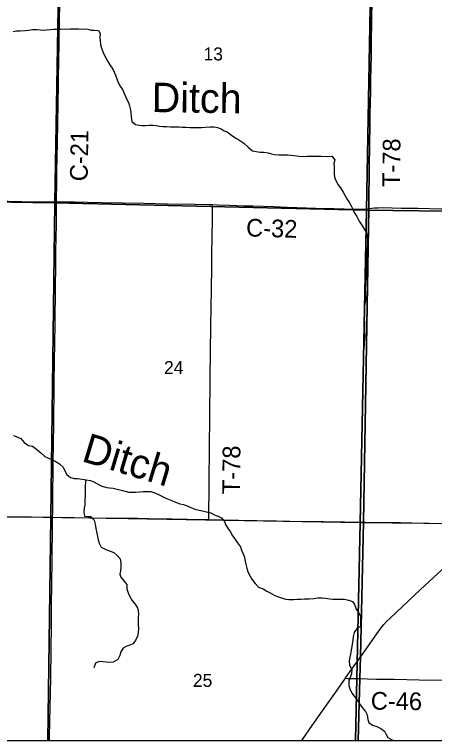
# Model space of a CAD drawing. Extents: x -8.5 to 18.7, y -20.3 to 7.
# Drawn here: x 9.055 to 11.753, y -20.262 to -15.596 of the extents above; entities that cross this region are included whole.
import ezdxf

# ---------------------------------------------------------------- set-up
doc = ezdxf.new("R2010")
doc.units = 0
for name, color, linetype in [('GM_X_Corporation', 7, 'Continuous'), ('GM_X_County_Road', 7, 'Continuous'), ('GM_X_County_Road_Text', 7, 'Continuous'), ('GM_X_Minor_River', 7, 'Continuous'), ('GM_X_Minor_River_Text', 7, 'Continuous'), ('GM_X_Section', 7, 'Continuous'), ('GM_X_Section_Text', 7, 'Continuous'), ('GM_X_State_Route', 7, 'Continuous'), ('GM_X_Township_Road', 7, 'Continuous'), ('GM_X_Township_Road_Text', 7, 'Continuous'), ('GM_X_Unincorporated_Text', 7, 'Continuous'), ('SH_Cut_Line', 7, 'Continuous')]:
    doc.layers.add(name, color=color, linetype=linetype)

msp = doc.modelspace()

# ---------------------------------------------------------------- linework, layer by layer
at = {"layer": 'GM_X_Corporation'}
for points in [[(-0.9232, -20.262), (11.2623, -20.262), (11.2736, -19.8636), (11.277, -19.7245), (11.2969, -18.8581), (11.3321, -16.8414), (11.3313, -16.8312), (11.331, -16.8266), (11.3309, -16.7927), (11.3361, -16.4073), (11.3374, -16.324), (11.339, -16.2358), (11.3417, -16.0903), (11.343, -16.0108), (11.3457, -15.8603), (11.3472, -15.7708), (11.351, -15.4961)], [(11.351, -15.4961), (11.3472, -15.7708), (11.3457, -15.8603), (11.343, -16.0108), (11.3417, -16.0903), (11.339, -16.2358), (11.3374, -16.324), (11.3361, -16.4073), (11.3309, -16.7927), (11.331, -16.8266), (11.3313, -16.8312), (11.3321, -16.8414), (11.2969, -18.8581), (11.277, -19.7245), (11.2736, -19.8636), (11.2623, -20.262), (18.7413, -20.262)]]:
    msp.add_lwpolyline(points, dxfattribs=at)
at = {"layer": 'GM_X_County_Road'}
for points in [[(9.3259, -16.7991), (9.326, -16.7709), (9.3266, -16.6901), (9.3279, -16.6018), (9.3308, -16.4216), (9.335, -16.1655), (9.3375, -16.0536), (9.3386, -15.9952), (9.3398, -15.9069), (9.3425, -15.7689), (9.3454, -15.6123), (9.3458, -15.5439), (9.3465, -15.5029), (9.3479, -15.4171), (9.3498, -15.3413), (9.3554, -15.0343), (9.3572, -14.9385), (9.3599, -14.7935)], [(7.3471, -16.771), (7.5621, -16.7748), (7.6354, -16.7759), (7.7299, -16.7774), (7.7908, -16.7785), (7.8902, -16.7802), (7.9735, -16.7818), (8.1998, -16.7851), (8.3067, -16.7862), (8.5131, -16.7898), (8.5566, -16.7903), (8.615, -16.7911), (8.7393, -16.7925), (8.8102, -16.7933), (8.9072, -16.7947), (9.0154, -16.7963), (9.1024, -16.7972), (9.264, -16.7988), (9.3137, -16.7991), (9.3259, -16.7991)], [(9.3003, -18.8271), (9.3007, -18.8058), (9.3006, -18.7374), (9.3021, -18.6504), (9.3042, -18.551), (9.3043, -18.4839), (9.306, -18.3496), (9.3078, -18.234), (9.3086, -18.1395), (9.3093, -18.0613), (9.3104, -17.9755), (9.3131, -17.8089), (9.3139, -17.7206), (9.3158, -17.574), (9.3187, -17.3564), (9.3206, -17.2047), (9.3216, -17.1289), (9.3233, -17.0182), (9.3245, -16.9574), (9.3246, -16.9101), (9.3258, -16.8305), (9.3259, -16.7991)], [(9.3259, -16.7991), (9.3966, -16.8), (9.4414, -16.8008), (9.5234, -16.8026), (9.6166, -16.804), (9.8864, -16.8089), (10.038, -16.812), (10.2133, -16.815), (10.3053, -16.8169), (10.3269, -16.8173)], [(10.3269, -16.8173), (10.3562, -16.818), (10.4358, -16.821), (10.5264, -16.8244), (10.5873, -16.8261), (10.7215, -16.8305), (10.8072, -16.8337), (10.9302, -16.8375), (11.0495, -16.8416), (11.1079, -16.8433), (11.2372, -16.8472), (11.2657, -16.8474), (11.2842, -16.8466), (11.3139, -16.8443), (11.3326, -16.8425)], [(11.3326, -16.8425), (11.3671, -16.8392), (11.392, -16.8377), (11.4257, -16.8371), (11.4804, -16.8379), (11.5413, -16.8394), (11.6494, -16.841), (11.7961, -16.8438), (11.8446, -16.8445), (12.0534, -16.8489), (12.1603, -16.8513), (12.2958, -16.8534), (12.4375, -16.8563), (12.4873, -16.8575), (12.532, -16.8584), (12.6066, -16.8592), (12.6538, -16.8603), (12.7657, -16.8621), (12.9099, -16.8649), (13.0167, -16.8667), (13.1821, -16.8697), (13.2828, -16.8711), (13.3593, -16.8726)], [(9.2795, -20.262), (9.2801, -20.2354), (9.2869, -19.9508), (9.289, -19.8662), (9.2893, -19.8078), (9.2903, -19.732), (9.2908, -19.635), (9.292, -19.5642), (9.2938, -19.3913), (9.2957, -19.2571), (9.2974, -19.0992), (9.2988, -18.8891), (9.3003, -18.8271)], [(11.1806, -19.862), (11.1973, -19.8626), (11.2363, -19.8639), (11.2741, -19.8647)], [(11.2741, -19.8647), (11.3221, -19.8657), (11.3817, -19.8672), (11.4936, -19.8684), (11.6552, -19.8712), (11.9747, -19.8761), (12.0692, -19.8767), (12.1997, -19.8796), (12.2954, -19.8809), (12.3998, -19.8829), (12.646, -19.8869), (12.7603, -19.8886), (12.8871, -19.8909), (13.0139, -19.8932), (13.0972, -19.8946), (13.1854, -19.8963), (13.3025, -19.8984)]]:
    msp.add_lwpolyline(points, dxfattribs=at)
at = {"layer": 'GM_X_Minor_River'}
for points in [[(9.0478, -15.7058), (9.0683, -15.7014), (9.0918, -15.7), (9.1236, -15.6994), (9.1456, -15.6957), (9.1699, -15.692), (9.1986, -15.6914), (9.2198, -15.6937)], [(9.2198, -15.6937), (9.2403, -15.6953), (9.26, -15.6947), (9.2858, -15.6925), (9.3062, -15.6903), (9.3274, -15.6897), (9.3509, -15.689), (9.3752, -15.6884), (9.3956, -15.6892), (9.4153, -15.6886), (9.4426, -15.6879), (9.4676, -15.6881), (9.4873, -15.6897), (9.507, -15.6882), (9.5274, -15.6906), (9.5471, -15.6953), (9.5675, -15.6969), (9.594, -15.6985), (9.6053, -15.7183), (9.603, -15.7433), (9.6052, -15.7631), (9.6081, -15.7889), (9.6148, -15.8117), (9.6283, -15.8497), (9.6426, -15.8748), (9.6546, -15.8968), (9.6674, -15.9189), (9.6862, -15.9463), (9.6945, -15.9668), (9.7043, -15.9866), (9.714, -16.0162), (9.7238, -16.036), (9.7335, -16.0557), (9.7486, -16.0778), (9.7584, -16.0968), (9.7689, -16.1219), (9.7779, -16.1417), (9.7884, -16.1622), (9.7944, -16.182), (9.8011, -16.2078), (9.8018, -16.2268), (9.804, -16.2533), (9.8092, -16.2837), (9.8326, -16.302), (9.856, -16.3074), (9.8757, -16.3091), (9.8969, -16.3084), (9.9212, -16.3062), (9.9439, -16.3063), (9.9659, -16.3095), (9.9871, -16.3126), (10.0083, -16.315), (10.031, -16.3159), (10.0567, -16.3175), (10.081, -16.3184), (10.1135, -16.3185), (10.1332, -16.3194), (10.1552, -16.3195), (10.1817, -16.3211), (10.2029, -16.3212), (10.2309, -16.3221), (10.2559, -16.3214), (10.2832, -16.3208), (10.312, -16.3187), (10.3363, -16.3173), (10.3597, -16.3212), (10.3824, -16.3311), (10.4021, -16.3426), (10.4225, -16.3495), (10.4497, -16.3709), (10.4776, -16.3908), (10.4973, -16.4007), (10.5275, -16.4221), (10.5554, -16.4473), (10.5841, -16.4709), (10.6068, -16.4771), (10.6326, -16.4802), (10.6568, -16.4804), (10.6841, -16.4843), (10.7052, -16.4912), (10.7257, -16.4951), (10.7537, -16.4967), (10.8098, -16.497), (10.8294, -16.5001), (10.8537, -16.5018), (10.8824, -16.5057), (10.9067, -16.5073), (10.9324, -16.5067), (10.9536, -16.506), (10.9847, -16.5069), (11.0044, -16.5062), (11.0256, -16.5071), (11.0688, -16.5073), (11.0945, -16.5067), (11.1134, -16.5303), (11.1072, -16.5538), (11.1079, -16.5727), (11.1093, -16.5978), (11.1085, -16.6167), (11.1099, -16.641), (11.1204, -16.6623)], [(11.1204, -16.6623), (11.1347, -16.6897), (11.149, -16.7087), (11.1656, -16.7369), (11.1799, -16.7605), (11.1904, -16.7802), (11.2078, -16.8054), (11.2183, -16.8244), (11.2296, -16.8479), (11.237, -16.8692), (11.2551, -16.8943), (11.2694, -16.9232), (11.2822, -16.943), (11.2988, -16.9704), (11.3146, -16.9948), (11.3213, -17.0175), (11.3235, -17.0464), (11.3234, -17.0729), (11.3202, -17.1018), (11.3186, -17.1215), (11.317, -17.1427), (11.3185, -17.1617), (11.3176, -17.1814), (11.3168, -17.2026), (11.3159, -17.2284), (11.3136, -17.2534), (11.3135, -17.2724), (11.3126, -17.2944), (11.3103, -17.3141), (11.3095, -17.3331), (11.3086, -17.3581), (11.31, -17.3854), (11.3107, -17.4105), (11.3091, -17.4347), (11.3067, -17.4545), (11.3036, -17.4734), (11.3012, -17.4992), (11.3026, -17.525), (11.3025, -17.5508), (11.3047, -17.5766), (11.3045, -17.6312), (11.3059, -17.6525), (11.3035, -17.6813), (11.3019, -17.7071), (11.3011, -17.7268)], [(9.0483, -18.302), (9.0763, -18.312)], [(9.0763, -18.312), (9.0959, -18.3204), (9.117, -18.347), (9.1457, -18.3654), (9.1707, -18.3708), (9.1956, -18.3899), (9.2236, -18.4135), (9.2492, -18.4372), (9.2689, -18.4456), (9.2901, -18.4533), (9.3165, -18.4671), (9.3445, -18.4846), (9.3686, -18.506), (9.3807, -18.5326), (9.392, -18.5516), (9.4146, -18.5707), (9.4396, -18.5784), (9.4593, -18.5785), (9.4895, -18.5824), (9.5153, -18.5863), (9.544, -18.5918), (9.5645, -18.6002), (9.5849, -18.6102), (9.6121, -18.6254), (9.6454, -18.6362), (9.6658, -18.6371), (9.6901, -18.6402), (9.7415, -18.6541), (9.7657, -18.6603), (9.7907, -18.6665), (9.8134, -18.6666), (9.8339, -18.6652), (9.8604, -18.6645), (9.8816, -18.6624), (9.9081, -18.661), (9.9301, -18.6618), (9.9505, -18.6672), (9.9755, -18.678), (10.0019, -18.6925), (10.0284, -18.704), (10.0488, -18.7124), (10.07, -18.7209), (10.0896, -18.7301), (10.1176, -18.7401), (10.1419, -18.7447), (10.1638, -18.7532), (10.188, -18.7654), (10.2137, -18.7754), (10.2409, -18.7816), (10.2621, -18.7862), (10.2894, -18.7924), (10.3159, -18.7994), (10.3446, -18.8139), (10.3643, -18.8201), (10.3854, -18.8308), (10.4035, -18.8536), (10.411, -18.8742), (10.4276, -18.9008), (10.4419, -18.9213), (10.4524, -18.9411), (10.4675, -18.9647), (10.4886, -18.9921), (10.5074, -19.018), (10.5141, -19.0385), (10.5231, -19.0575), (10.5299, -19.0772), (10.5373, -19.1084), (10.5418, -19.1281), (10.547, -19.1554), (10.5545, -19.179), (10.5688, -19.2056), (10.5808, -19.2254), (10.6004, -19.2535), (10.6238, -19.2756), (10.6525, -19.2879), (10.6759, -19.3032), (10.6971, -19.3139), (10.7281, -19.33), (10.7508, -19.3392), (10.7765, -19.3476), (10.7984, -19.353), (10.8181, -19.3562), (10.8484, -19.3548), (10.8704, -19.3534), (10.8939, -19.3535), (10.9181, -19.3513), (10.9492, -19.3515), (10.9787, -19.3501), (11.0037, -19.3457), (11.031, -19.3458), (11.0545, -19.3482), (11.081, -19.3521), (11.1007, -19.3537), (11.1211, -19.3546), (11.1431, -19.3547), (11.1726, -19.354), (11.2037, -19.3595), (11.2271, -19.3687), (11.2392, -19.3885), (11.2512, -19.4174), (11.267, -19.444)], [(9.5145, -18.5862), (9.5122, -18.6007), (9.5098, -18.6265), (9.5096, -18.6743), (9.5079, -18.7289), (9.5063, -18.7478), (9.5032, -18.7668), (9.5008, -18.7941), (9.506, -18.8199), (9.5265, -18.8223), (9.5462, -18.8216), (9.568, -18.846), (9.5732, -18.8725), (9.5784, -18.8999), (9.5851, -18.9287), (9.5881, -18.95), (9.5925, -18.9728), (9.5993, -18.9933), (9.6128, -19.0191), (9.6423, -19.0344), (9.6665, -19.0429), (9.6929, -19.0544), (9.7179, -19.0742), (9.7344, -19.0955), (9.7389, -19.1229), (9.738, -19.1524), (9.7364, -19.1714), (9.7325, -19.1926), (9.7378, -19.2124), (9.7581, -19.2352), (9.7777, -19.2588), (9.7776, -19.2869), (9.7851, -19.3134), (9.7994, -19.3401), (9.8099, -19.3591), (9.828, -19.3834), (9.8453, -19.4101), (9.8505, -19.429), (9.8512, -19.448), (9.8503, -19.4738), (9.8487, -19.4935), (9.8501, -19.5193), (9.8516, -19.5428), (9.8499, -19.5686), (9.8453, -19.5913), (9.8331, -19.6201), (9.8163, -19.6405), (9.7966, -19.6495), (9.7769, -19.6555), (9.7526, -19.6683), (9.7388, -19.6932), (9.7312, -19.7152), (9.7197, -19.7417), (9.6893, -19.759), (9.6666, -19.7611), (9.6462, -19.758), (9.6242, -19.7556), (9.6, -19.7548), (9.5757, -19.7645), (9.5657, -19.7948)], [(11.267, -19.444), (11.2775, -19.4637), (11.2774, -19.4865), (11.2781, -19.5062), (11.278, -19.529), (11.2575, -19.541), (11.2369, -19.5682), (11.2315, -19.5947), (11.2284, -19.6175), (11.2222, -19.6577), (11.2175, -19.6804), (11.2129, -19.7062), (11.2098, -19.7259), (11.2051, -19.7509), (11.2073, -19.7789), (11.2216, -19.8063), (11.2192, -19.8306), (11.2115, -19.8563), (11.2038, -19.8806), (11.2037, -19.9079), (11.2105, -19.9291), (11.2225, -19.9572), (11.2443, -19.9854), (11.2586, -20.0052), (11.2707, -20.0265), (11.2888, -20.0509), (11.3106, -20.0767), (11.3211, -20.098), (11.3248, -20.1269), (11.3323, -20.1459), (11.3542, -20.1634), (11.3837, -20.1711), (11.4087, -20.1841), (11.4328, -20.2025), (11.4418, -20.223), (11.4539, -20.242), (11.4818, -20.2588), (11.4903, -20.262)]]:
    msp.add_lwpolyline(points, dxfattribs=at)
at = {"layer": 'GM_X_Section'}
for points in [[(7.3681, -14.7705), (9.3493, -14.7982), (9.3147, -16.8052), (7.3365, -16.776)], [(9.3493, -14.7982), (11.3525, -14.8396), (11.3171, -16.8542), (9.3147, -16.8052)], [(11.3525, -14.8396), (11.3525, -14.8313), (13.3845, -14.866), (13.3536, -16.8784), (11.3171, -16.8542)], [(7.3365, -16.776), (9.3147, -16.8052), (9.2884, -18.8288), (7.2987, -18.8185)], [(9.3147, -16.8052), (11.3171, -16.8542), (11.2748, -18.8626), (9.2884, -18.8288)], [(11.3171, -16.8542), (13.3536, -16.8784), (13.322, -18.8853), (11.2748, -18.8626)]]:
    msp.add_lwpolyline(points, close=True, dxfattribs=at)
at = {"layer": 'GM_X_State_Route'}
for points in [[(11.2763, -19.7271), (11.2774, -19.7256), (11.3834, -19.5764), (11.4112, -19.537), (11.4283, -19.516), (11.4453, -19.498), (11.4687, -19.4748), (11.6608, -19.2934), (11.8019, -19.1622), (11.9683, -19.0034), (12.0706, -18.9071), (12.1075, -18.8708), (12.1214, -18.8577), (12.2722, -18.7091), (12.4429, -18.5376), (12.6032, -18.3814), (12.786, -18.2054), (12.8835, -18.1111), (12.9398, -18.0585), (13.0495, -17.9554), (13.2278, -17.7901), (13.3125, -17.7108), (13.3521, -17.673)], [(10.9019, -20.262), (10.9534, -20.1876), (11.0385, -20.065), (11.1121, -19.9602), (11.1806, -19.862), (11.1825, -19.8593), (11.2653, -19.7427), (11.2763, -19.7271)]]:
    msp.add_lwpolyline(points, dxfattribs=at)
at = {"layer": 'GM_X_Township_Road'}
for points in [[(11.3326, -16.8425), (11.3318, -16.8323), (11.3314, -16.8277), (11.3313, -16.7938), (11.3365, -16.4084), (11.3379, -16.3251), (11.3395, -16.2369), (11.3422, -16.0914), (11.3434, -16.0119), (11.3461, -15.8614), (11.3476, -15.7719), (11.3514, -15.4972), (11.3527, -15.3641), (11.359, -14.9589), (11.3615, -14.8482), (11.3623, -14.831)], [(10.3039, -18.8413), (10.3039, -18.8289), (10.3042, -18.7879), (10.3048, -18.6573), (10.3063, -18.5268), (10.3072, -18.4547), (10.3088, -18.3429), (10.3097, -18.2185), (10.3111, -18.0868), (10.3115, -18.0271), (10.3129, -17.9426), (10.3154, -17.7511), (10.317, -17.6119), (10.3189, -17.4615), (10.3201, -17.3794), (10.3224, -17.2017), (10.3232, -17.147), (10.3252, -17.0164), (10.3262, -16.922), (10.3263, -16.9046), (10.3263, -16.9008), (10.3262, -16.8884), (10.3264, -16.8579), (10.3264, -16.8453), (10.3268, -16.8244), (10.3269, -16.8173)], [(10.3269, -16.8173), (10.3562, -16.818), (10.4358, -16.821), (10.5264, -16.8244), (10.5873, -16.8261), (10.7215, -16.8305), (10.8072, -16.8337), (10.9302, -16.8375), (11.0495, -16.8416), (11.1079, -16.8433), (11.2372, -16.8472), (11.2657, -16.8474), (11.2842, -16.8466), (11.3139, -16.8443), (11.3326, -16.8425)], [(7.3123, -18.8162), (7.3484, -18.8159), (7.4367, -18.8151), (7.5162, -18.8146), (7.561, -18.8146), (7.6505, -18.8135), (7.6803, -18.8135), (7.7885, -18.8135), (7.8195, -18.813), (7.8444, -18.813), (7.8668, -18.8132), (7.9699, -18.8134), (8.0905, -18.8131), (8.2385, -18.8132), (8.3305, -18.8135), (8.5033, -18.815), (8.609, -18.8168), (8.8439, -18.8203), (8.9334, -18.8217), (9.0851, -18.8237), (9.1647, -18.8251), (9.2405, -18.8263), (9.2865, -18.827), (9.3003, -18.8271)], [(9.3003, -18.8271), (9.3587, -18.8277), (9.4382, -18.8286), (9.5526, -18.8307), (9.6446, -18.8322), (9.7105, -18.8334), (9.7987, -18.8333), (9.8472, -18.8337), (9.9143, -18.8347), (10.0673, -18.8372), (10.1655, -18.8388), (10.2861, -18.8409), (10.3039, -18.8413)], [(10.3039, -18.8413), (10.4937, -18.8452), (10.6118, -18.8478), (10.7386, -18.8505), (10.9114, -18.8536), (11.0382, -18.8555), (11.1103, -18.8564), (11.175, -18.8574), (11.2973, -18.8592)], [(11.2973, -18.8592), (11.308, -18.8593), (11.4373, -18.8612), (11.5343, -18.8619), (11.6101, -18.8632), (11.8252, -18.8669), (11.8451, -18.8671), (11.8712, -18.8674), (11.9048, -18.8678), (11.9408, -18.8685), (11.9719, -18.8691), (11.998, -18.8696), (12.034, -18.8705), (12.0802, -18.8708), (12.0926, -18.8711), (12.1075, -18.8708)]]:
    msp.add_lwpolyline(points, dxfattribs=at)
at = {"layer": 'GM_X_Unincorporated_Text'}
for points in [[(7.2687, -20.262), (9.2701, -20.262), (9.2884, -18.8288), (7.2987, -18.8185)], [(9.2701, -20.262), (11.2465, -20.262), (11.2748, -18.8626), (9.2884, -18.8288)], [(11.2465, -20.262), (13.2833, -20.262), (13.322, -18.8853), (11.2748, -18.8626)]]:
    msp.add_lwpolyline(points, close=True, dxfattribs=at)
at = {"layer": 'SH_Cut_Line'}
msp.add_lwpolyline([(-8.4587, -10.6981), (-8.4587, -20.262), (18.7413, -20.262), (18.7413, -10.9039)], dxfattribs=at)

# ---------------------------------------------------------------- texts
at = {"layer": 'GM_X_County_Road_Text'}
for s, rotation, p in [('C-21', 88.9772, (9.5248, -16.6682)), ('C-32', 358.2857, (10.5417, -17.0217)), ('C-46', 359.3122, (11.3434, -20.0635))]:
    msp.add_text(s, height=0.11364, rotation=rotation, dxfattribs=at).set_placement(p)
at = {"layer": 'GM_X_Minor_River_Text'}
for height, rotation, p in [(0.18948, 359.2119, (9.9358, -16.2227)), (0.18947, 343.2138, (9.4793, -18.4648))]:
    msp.add_text('Ditch', height=height, rotation=rotation, dxfattribs=at).set_placement(p)
at = {"layer": 'GM_X_Section_Text'}
for s, p in [('13', (10.2698, -15.8909)), ('24', (10.0157, -17.907)), ('25', (10.2015, -19.9176))]:
    msp.add_text(s, height=0.08371, rotation=0, dxfattribs=at).set_placement(p)
at = {"layer": 'GM_X_Township_Road_Text'}
for rotation, p in [(89.2931, (11.5312, -16.7051)), (89.3025, (10.5029, -18.6793))]:
    msp.add_text('T-78', height=0.11364, rotation=rotation, dxfattribs=at).set_placement(p)

doc.saveas('drawing.dxf')
